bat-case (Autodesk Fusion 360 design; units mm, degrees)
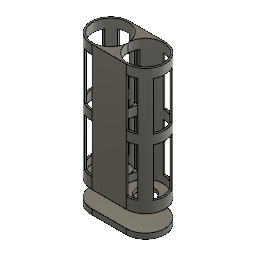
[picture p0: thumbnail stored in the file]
sketch "Sketch1" plane through (0, 0, 0) normal (0, 1, 0) x axis (1, 0, 0)
  line L1 (15, 15) -> (5, 15)
  line L2 (15, -15) -> (15, 15)
  line L3 (5, -15) -> (15, -15)
  line L4 (5, 15) -> (5, -15)
  line L5 (33.5, 15) -> (23.5, 15)
  line L6 (33.5, -15) -> (33.5, 15)
  line L7 (23.5, -15) -> (33.5, -15)
  line L8 (23.5, 15) -> (23.5, -15)
  line L9 (44, 5) -> (-5, 5)
  line L10 (44, -5) -> (44, 5)
  line L11 (-5, -5) -> (44, -5)
  line L12 (-5, 5) -> (-5, -5)
  line L13 (10, 13) -> (10, -19)
  line L14 (28.5, -19) -> (28.5, 0)
  line L15 (28.5, 13) -> (28.5, -19)
  line L16 (28.5, 10.5) -> (10, 10.4881)
  line L17 (28.5, -10.5) -> (10, -10.4881)
  circle C1 centre (9.5, 0) radius 9.5
  circle C2 centre (9.5, 0) radius 10.5
  circle C3 centre (28.5, 0) radius 9.5
  circle C4 centre (28.5, 0) radius 10.5
  circle C5 centre (10, 0) radius 5
  circle C6 centre (28.5, 0) radius 5
  point P1 (0, 0)
  point P7 (28.5, 0)
  point P22 (28.5, 0)
  point P25 (10, 10.4881)
  point P26 (28.5, 10.5)
  point P27 (10, -10.4881)
  point P28 (28.5, -10.5)
  coincident P1 C1
  concentric C4 C6
  horizontal L1
  vertical L2
  horizontal L3
  vertical L4
  horizontal L5
  vertical L6
  horizontal L7
  vertical L8
  horizontal L9
  vertical L10
  horizontal L11
  vertical L12
  vertical L13
  coincident P7 P22
  vertical L14
  perpendicular L7 L15
  coincident L13 P25
  coincident C2 P25
  coincident L15 P26
  coincident C4 P26
  coincident L13 P27
  coincident C2 P27
  coincident L14 P28
  coincident C4 P28
  dimension "d31" diameter C1 = 19
  dimension "d32" diameter C3 = 19
  dimension "d35" diameter C6 = 10
extrude "Extrude15" new body sketch "Sketch1" profile of C1 C2 C3 C4 C5 C6 L2 L4 L6 L8 L9 L11 L13 L14 L15 L16 L17 along normal blind 3
extrude "Extrude8" new body sketch "Sketch1" profile of C1 C2 C3 C4 C5 C6 against normal blind 1
extrude "Extrude7" new body sketch "Sketch1" profile of C1 C2 C3 C4 along normal blind 66
extrude "Extrude1" new body sketch "Sketch1" along normal blind 65
extrude "Extrude2" new body sketch "Sketch1" against normal blind 1
combine "Combine1"
extrude "Extrude3" cut sketch "Sketch1" against normal blind 5
box_primitive "BoxPrimitive1" DistanceX 20 DistanceY 74 DistanceZ -1 OffsetDistanceX 0 OffsetDistanceY 0
extrude "Extrude4" cut sketch "Sketch1" against normal blind 2
extrude "Extrude5" add of existing geometry blind 1 from offset 64
extrude "Extrude6" add of existing geometry blind 64
extrude "Extrude9" cut sketch "Sketch1" profile of C1 C2 C3 C4 C5 C6 L1 L2 L3 L4 L5 L6 L7 L8 blind 57 from offset 4
extrude "Extrude10" cut sketch "Sketch1" profile of C1 C2 C3 C4 C5 C6 L2 L4 L6 L8 L9 L10 L11 L12 blind 57 from offset 4
extrude "Extrude11" add sketch "Sketch1" profile of C1 C2 C3 C4 L2 L8 L9 L11 L13 L14 L15 L16 L17 along normal blind 66
extrude "Extrude12" add sketch "Sketch1" profile of C2 C4 L2 L8 L9 L11 L16 L17 against normal blind 1
extrude "Extrude13" add of existing geometry blind 1
extrude "Extrude14" add sketch "Sketch1" profile of C1 C2 C3 C4 L2 L4 L6 L8 L9 L11 L13 L14 L15 L17 blind 5 from offset 30
move "Move1"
